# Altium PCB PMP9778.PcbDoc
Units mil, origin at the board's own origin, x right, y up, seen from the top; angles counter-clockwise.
Board outline 1070 x 670 mil, 4 copper layers (Top Layer, GND1, GND2, Bottom Layer), stack 82.634 mil thick; 30 components, 18 nets, 77 pads, 46 vias.
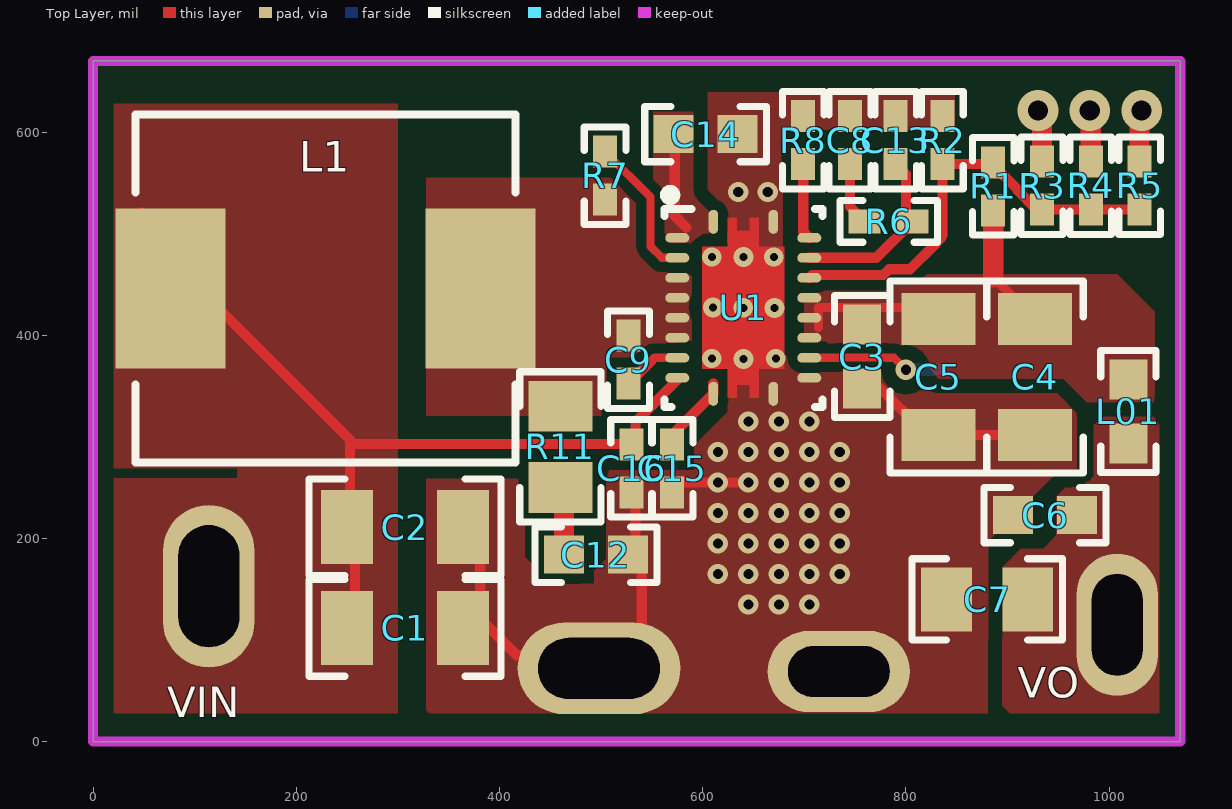
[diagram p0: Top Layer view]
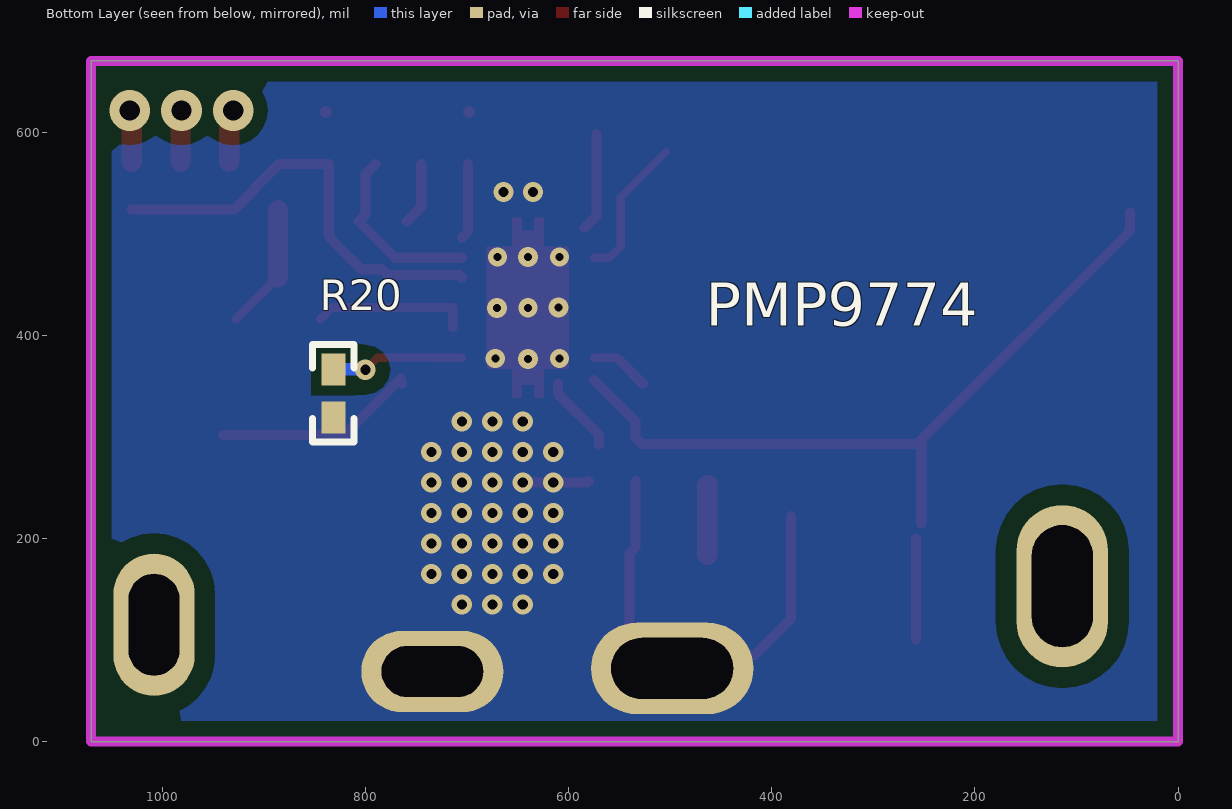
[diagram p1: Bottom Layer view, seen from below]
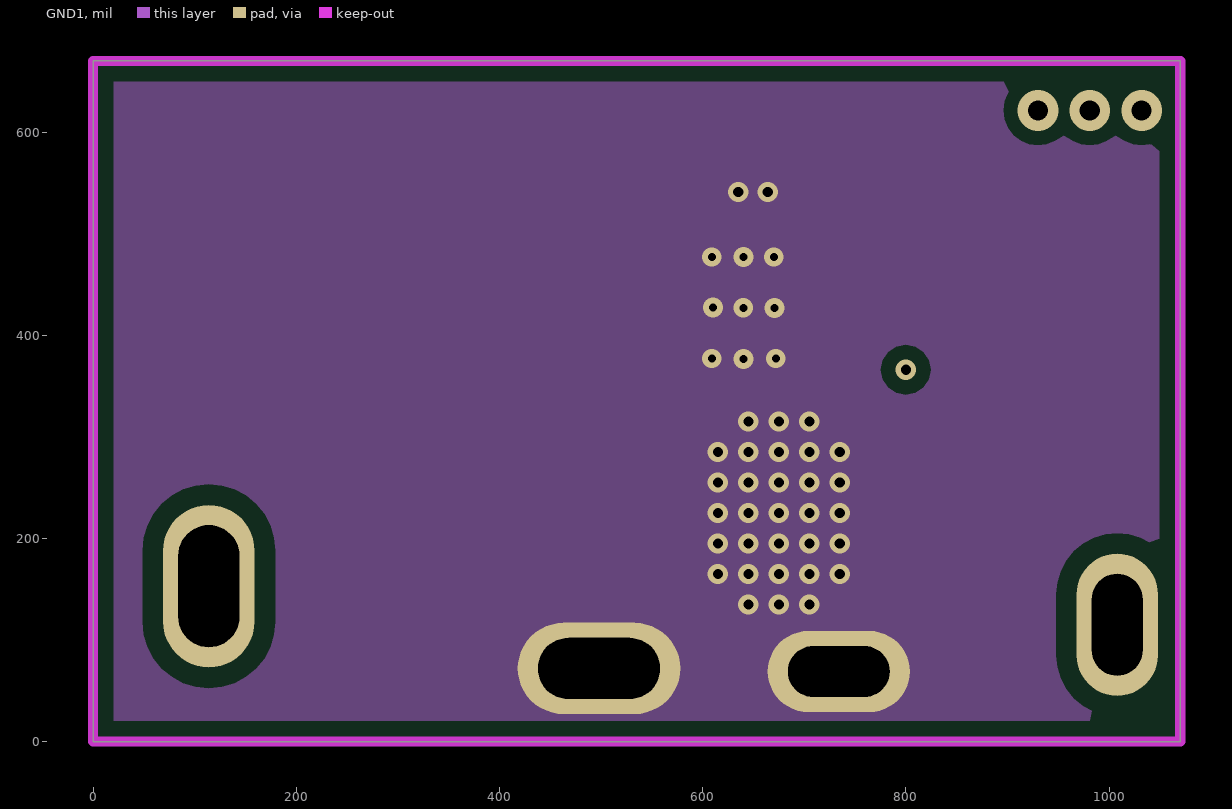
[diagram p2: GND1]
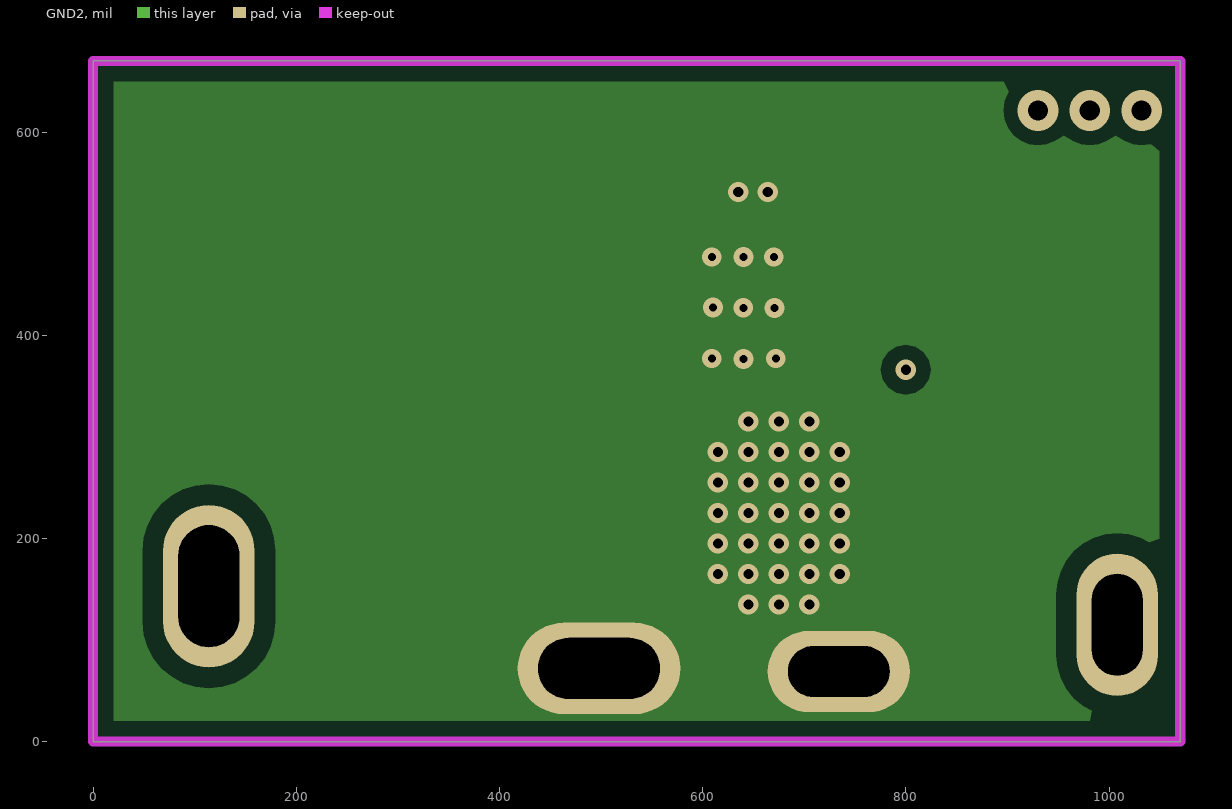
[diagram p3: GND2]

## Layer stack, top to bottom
Top Solder: solder mask 0.4, Solder Resist, Dk 3.5
Top Layer: signal copper 2.8
Dielectric1: core 59.2, FR-4, Dk 4.8
GND1: signal copper 1.417
Dielectric 3: prepreg 5, Dk 4.2
GND2: signal copper 1.417
Dielectric 2: core 10, Dk 4.2
Bottom Layer: signal copper 2.8
Bottom Solder: solder mask 0.4, Solder Resist, Dk 3.5

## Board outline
0,0 0,670 1070,670 1070,0

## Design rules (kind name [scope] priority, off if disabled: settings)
AcuteAngle [All] p1: minimum=4.50000000000000E+0001 checktracksonly=FALSE
AssemblyTestPointUsage [All] p1: valid=2
Clearance Clearance_BoardEdge_MountingHoles [OnCopper and InComponentClass('Mounting Holes') vs IsKeepOut] p1: gap=40
Clearance Clearance_BoardEdge_Poly [OnCopper and InPoly vs IsKeepOut] p2: gap=20 except(15: Arc-Poly Track-Poly SMDPad-Poly THPad-Poly Via-Poly Fill-Poly Poly-Poly Poly-Region Poly-Text)
Clearance Clearance_BoardEdge [All vs IsKeepOut] p3 off: gap=75
Clearance Clearance_Poly [InPolygon] p4: gap=20 except(10: Track-Poly SMDPad-Poly Poly-Region; 14: Via-Poly Fill-Poly Poly-Poly)
Clearance [All] p5: gap=7 except(5: THPad-Via Via-Via)
ComponentClearance ComponentClearance_Logo [InComponentClass('Logo')] p1: gap=50 collisioncheckmode=3 verticalgap=10 showdistances=FALSE
ComponentClearance ComponentClearance_ScrewToNut [(HasFootprint('NY PMS 440 0025 PH')) vs (HasFootprint('Keystone_1902C'))] p2: gap=0.5 collisioncheckmode=3 verticalgap=0.5 showdistances=FALSE
ComponentClearance ComponentClearance_MountingHoles [InComponentClass('Mounting Holes')] p3 off: gap=250 collisioncheckmode=3 verticalgap=100000 showdistances=FALSE
ComponentClearance ComponentClearance_SmallPassives [HasFootprint('0201*') or HasFootprint('0402*') or HasFootprint('0508') or HasFootprint('0603*') or HasFootprint('0612') or HasFootprint('0805*') or HasFootprint('0815*') or HasFootprint('0830*') or HasFootprint('1206*') or HasFootprint('1210*') or HasFootprint('1808*') or HasFootprint('1812*') or HasFootprint('1825*') or HasFootprint('2010*') or HasFootprint('2220*') or HasFootprint('2225*') or HasFootprint('2512*') or HasFootprint('2728*') or HasFootprint('3518*') vs HasFootprint('0201*') or HasFootprint('0402*') or HasFootprint('0508') or HasFootprint('0603*') or HasFootprint('0612') or HasFootprint('0805*') or HasFootprint('0815*') or HasFootprint('0830*') or HasFootprint('1206*') or HasFootprint('1210*') or HasFootprint('1808*') or HasFootprint('1812*') or HasFootprint('1825*') or HasFootprint('2010*') or HasFootprint('2220*') or HasFootprint('2225*') or HasFootprint('2512*') or HasFootprint('2728*') or HasFootprint('3518*')] p4: gap=5 collisioncheckmode=3 verticalgap=5 showdistances=FALSE
ComponentClearance ComponentClearance_THtoSMT [IsThruComponent vs IsSMTComponent] p5: gap=5 collisioncheckmode=3 verticalgap=5 showdistances=FALSE
ComponentClearance ComponentClearance_THtoTH [IsThruComponent vs IsThruComponent] p6: gap=5 collisioncheckmode=3 verticalgap=30 showdistances=FALSE
ComponentClearance [All] p7: gap=5 collisioncheckmode=3 verticalgap=5 showdistances=FALSE
DiffPairsRouting [All] p1: maxlimit=100 minlimit=10 mostfreqgap=10 toplayer_minwidth=15 toplayer_maxwidth=15 toplayer_prefwidth=15 midlayer1_minwidth=15 midlayer1_maxwidth=15 midlayer1_prefwidth=15 midlayer2_minwidth=15 midlayer2_maxwidth=15 midlayer2_prefwidth=15 bottomlayer_minwidth=15 bottomlayer_maxwidth=15 bottomlayer_prefwidth=15 maxuncoupledlength=1000
FabricationTestPointUsage TestPointUsage [All] p1: valid=2 allowmultiple=FALSE
FabricationTestpoint Testpoint [All] p1: side=3 testpointundercomponent=TRUE minsize=40 maxsize=100 preferedsize=60 minholesize=0 maxholesize=40 preferedholesize=32 testpointgrid=1 allowsidetop=TRUE allowsidebottom=TRUE usegrid=TRUE gridtolerance=0.01
FanoutControl Fanout_LCC [IsLCC] p1: bgadir=Out bgaviamode=Centered fanoutstyle=Auto fanoutdirection=Alternating viagrid=1 // Fanout_LCC (Default Rule)
FanoutControl Fanout_BGA [IsBGA] p2: bgadir=Out bgaviamode=Centered fanoutstyle=Auto fanoutdirection=Alternating viagrid=1 // Fanout_BGA (Default Rule)
FanoutControl Fanout_Default [All] p4: bgadir=Out bgaviamode=Centered fanoutstyle=Auto fanoutdirection=Alternating viagrid=1 // Fanout_Default (Default Rule)
FanoutControl Fanout_Small [(CompPinCount < 5)] p5: bgadir=Out bgaviamode=Centered fanoutstyle=Auto fanoutdirection=OutThenIn viagrid=1 // Fanout_Small (Default Rule)
HoleSize [All] p1: absolutevalues=TRUE maxlimit=251 minlimit=7.87 maxpercent=80.000 minpercent=20.000
MinimumAnnularRing MinimumAnnularRing_ThermalPadVias [IsVia and InAnyComponent] p1: minimumring=5.91
MinimumAnnularRing [All] p2: minimumring=5
MinimumSolderMaskSliver MinimumSolderMaskSliver_Logo [InComponentClass('Logo') vs InComponentClass('Logo')] p1: minsoldermaskwidth=0.7
MinimumSolderMaskSliver [All] p2: minsoldermaskwidth=4
PlaneConnect [All] p1: planeconnectstyle=Direct reliefexpansion=10 reliefentries=4 reliefconductorwidth=10 reliefairgap=10
PolygonConnect PolygonConnect_5 [All vs IsNamedPolygon('Top Layer-No Net')] p1: connectstyle=Direct reliefconductorwidth=10 reliefentries=4 polygonreliefangle="90 Angle" airgapwidth=10
PolygonConnect PolygonConnect_4 [All] p2: connectstyle=Direct reliefconductorwidth=10 reliefentries=4 polygonreliefangle="90 Angle" airgapwidth=10
PolygonConnect PolygonConnect_3 [All vs IsNamedPolygon('Top Layer-No Net')] p3: connectstyle=Direct reliefconductorwidth=10 reliefentries=4 polygonreliefangle="90 Angle" airgapwidth=10
PolygonConnect PolygonConnect_2 [All vs IsNamedPolygon('Bottom Layer-No Net')] p4: connectstyle=Direct reliefconductorwidth=10 reliefentries=4 polygonreliefangle="90 Angle" airgapwidth=10
PolygonConnect PolygonConnect_1 [All vs IsNamedPolygon('Bottom Layer-No Net')] p5: connectstyle=Direct reliefconductorwidth=10 reliefentries=4 polygonreliefangle="90 Angle" airgapwidth=10
PolygonConnect [All] p6: connectstyle=Direct reliefconductorwidth=10 reliefentries=4 polygonreliefangle="90 Angle" airgapwidth=10
RoutingVias ThermalPadVias [IsVia and InAnyComponent] p1: holewidth=7.87 width=19.68 viastyle="Through Hole" minholewidth=7.87 minwidth=19.68 maxholewidth=12.99 maxwidth=23.62
RoutingVias [All] p2: holewidth=16 width=34 viastyle="Through Hole" minholewidth=7.87 minwidth=16 maxholewidth=40 maxwidth=65
SMDToCorner [All] p1 off: distance=30000
SilkToBoardRegionClearance [All] p1 off:
SilkToSilkClearance SilkToSilkClearance_PB-Free [(HasFootprint('Pb-Free_Overlay_Medium') OR HasFootprint('Pb-Free_Overlay_Small')) vs (HasFootprint('Pb-Free_Overlay_Medium') OR HasFootprint('Pb-Free_Overlay_Small'))] p1: silktosilkclearance=0
SilkToSilkClearance [All] p2: silktosilkclearance=4
SilkToSolderMaskClearance SilkscreenOverComponentPads [IsPad] p1: minsilkscreentomaskgap=3 clearancetoexposedcopper=TRUE
SolderMaskExpansion [All] p1: expansion=1
Width [All] p1: maxlimit=100 minlimit=6 preferedwidth=10 checkconnectedcopper=TRUE
15 further rules are at their usual default settings.

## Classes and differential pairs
component class Reference2_Hardware: !PCB ZZ1 ZZ2 ZZ3
component class Reference2: C1 C2 C4 C5 C6 C7 C8 C9 C12 C13 C14 C15 C16 L1 L01 R1 R2 R3 R4 R5 R6 R7 R8 R11 R20 U1
component class AssemblyNote: ZZ1 ZZ2 ZZ3

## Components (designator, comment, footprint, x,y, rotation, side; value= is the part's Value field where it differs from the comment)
C1 "GRM31CR61C226KE15L" 1206 307,112 r0 top
C2 "GRM31CR61C226KE15L" 1206 307,211 r0 top
C3 "GRM188R71E105KA12D" 0603 757,379 r270 top
C4 "GRM31CR61C226KE15L" 1206 927,359 r270 top
C5 "GRM31CR61C226KE15L" 1206 832,359 r270 top
C6 "GRM188R71E103KA01D" 0603 937,223 r180 top
C7 "GRM219R61E106KA12" 0805_HV 880,140 r180 top
C8 "GRM155R61H472KA01D" 0402 745,592 r90 top
C9 "GRM155R61C104KA88D" 0402 527,376 r270 top
C12 "GRM1885C1H222JA01D" 0603 495,184 r0 top
C13 "GRM1555C1H470FA01D" 0402 790,592 r90 top
C14 "0603ZD475KAT2A" 0603 603,598 r180 top
C15 "GRM155R71C473KA01D" 0402 570,269 r90 top
C16 "GRM155R61C104KA88D" 0402 530,269 r270 top
L1 "CDMC8D28NP-1R2MC" CDMC8D28 225,445 r0 top
L01 "BLM18SG121TN1D" 0603 1019,325 r270 top
R1 "CRCW0402768KFKED" 0402 886,546.62 r270 top
R2 "CRCW0402120KFKED" 0402 836,592 r270 top
R3 "CRCW0402120KFKED" 0402 934,547.24 r270 top
R4 "CRCW0402120KFKED" 0402 982,547.24 r270 top
R5 "CRCW0402100KFKED" 0402 1030,547.24 r90 top
R6 "CRCW040217K4FKED" 0402 783,512 r0 top
R7 "CRCW0402330KJNED" 0402 504,557 r270 top
R8 "CRCW0402100KFKED" 0402 699,592 r270 top
R11 "CRCW08051R00FKEA" 0805_HV 460,290 r270 top
R20 "RC0402JR-070RL" 0402 831.58,342.88 r90 bottom
U1 "TPS61088RHLR" RHL0020A 640,427 r0 top
ZZ1 "These assemblies are ESD sensitive, ESD precautions shall be observed." AssemblyNote 4010,3305 r90 top
ZZ2 "These assemblies must be clean and free from flux and all contaminants. Use of no clean flux is not acceptable." AssemblyNote 4005,2895 r90 top
ZZ3 "These assemblies must comply with workmanship standards IPC-A-610 Class 2, unless otherwise specified." AssemblyNote 4010,2475 r90 top

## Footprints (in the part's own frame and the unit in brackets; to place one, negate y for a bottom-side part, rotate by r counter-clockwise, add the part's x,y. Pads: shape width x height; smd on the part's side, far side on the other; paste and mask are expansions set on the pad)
0402 [mm] "0402 from SM-752 data"
  rect 0.8x0.6 smd: 1(-0.6,0) 2(0.6,0)
  silkscreen extent -1.22,-0.52 1.22,0.52, body extent -0.55,-0.3 0.55,0.3, height 0.6
0603 [mm] "0603 from SM-752 data"
  rect 1x0.95 smd: 1(-0.8,0) 2(0.8,0)
  silkscreen extent -1.52,-0.69 1.52,0.69, body extent -0.87,-0.47 0.87,0.47, height 1
0805_HV [mil] "0805 with 30mil clearance between pads"
  rect 50x63 smd: 1(-40,0) 2(40,0)
  silkscreen extent -74,-40 74,40, body extent -43,-29 43,29, height 57
1206 [mm] "1206 from SM-752 data"
  rect 1.3x1.85 smd: 1(-1.45,0) 2(1.45,0)
  silkscreen extent -2.4,-1.21 2.4,1.21, body extent -1.7,-0.9 1.7,0.9, height 1.35
AssemblyNote [mil] "Assembly Note"
CDMC8D28 [mm] "SMD, 2-Leads, Body 9.5x8.7mm"
  rect 2.75x4 smd: 1(-3.773,0.025) 2(3.977,0.025)
  silkscreen extent -4.65,-4.32 4.85,4.38, body extent -4.65,-4.32 4.85,4.38, height 3
RHL0020A [mm] "QFN, 20-Leads, Body 4.5x3.5mm, Pitch 0.5mm, Thermal Pad 3.05x2.05mm, TI Recommended"
  oval 0.24x0.6 smd: 1(-0.75,2.15) 10(-0.75,-2.15) 11(0.75,-2.15) 20(0.75,2.15)
  oval 0.6x0.24 smd: 2(-1.65,1.75) 3(-1.65,1.25) 4(-1.65,0.75) 5(-1.65,0.25) 6(-1.65,-0.25) 7(-1.65,-0.75) 8(-1.65,-1.25) 9(-1.65,-1.75) 12(1.65,-1.75) 13(1.65,-1.25) 14(1.65,-0.75) 15(1.65,-0.25) 16(1.65,0.25) 17(1.65,0.75) 18(1.65,1.25) 19(1.65,1.75)
  rect 0.3x0.3 smd paste-0.15 mask+0: 21(0,0)
  Top Layer region: 0.16,2.25 0.16,1.925 -0.16,1.925 -0.16,2.25 -0.39,2.25 -0.39,1.525 -1.025,1.525 -1.025,-1.525 -0.39,-1.525 -0.39,-2.25 -0.16,-2.25 -0.16,-1.925 0.16,-1.925 0.16,-2.25 0.39,-2.25 0.39,-1.525 1.025,-1.525 1.025,1.525 0.39,1.525 0.39,2.25
  silkscreen extent -1.98,-2.47 1.98,2.47, body extent -1.82,-2.33 1.83,2.32, height 1.01

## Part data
C1 C2 C4 C5: "CAP, CERM, 22 µF, 16 V, +/- 10%, X5R, 1206"
C3: "CAP, CERM, 1 µF, 25 V, +/- 10%, X7R, 0603"
C6: "CAP, CERM, 0.01 µF, 25 V, +/- 10%, X7R, 0603"
C7: "CAP, CERM, 10 µF, 25 V, +/- 10%, X5R, 0805"
C8: "CAP, CERM, 4700 pF, 50 V, +/- 10%, X5R, 0402"
C9 C16: "CAP, CERM, 0.1uF, 16V, +/-10%, X5R, 0402"
C12: "CAP, CERM, 2200 pF, 50 V, +/- 5%, C0G/NP0, 0603"
C13: "CAP, CERM, 47 pF, 50 V, +/- 1%, C0G, 0402"
C14: "CAP, CERM, 4.7uF, 10V, +/-10%, X5R, 0603"
C15: "CAP, CERM, 0.047 µF, 16 V, +/- 10%, X7R, 0402"
L1: "Inductor, Shielded Drum Core, Metal Composite, 1.2 µH, 12.9 A, 0.007 ohm, SMD"
L01: "Ferrite Bead, 120 ohm @ 100 MHz, 3 A, 0603"
R1: "RES, 768 k, 1%, 0.063 W, 0402"
R2 R3 R4: "RES, 120 k, 1%, 0.063 W, 0402"
R5 R8: "RES, 100k ohm, 1%, 0.063W, 0402"
R6: "RES, 17.4k ohm, 1%, 0.063W, 0402"
R7: "RES, 330 k, 5%, 0.063 W, 0402"
R11: "RES, 1.00, 1%, 0.125 W, 0805"
R20: "RES, 0, 5%, 0.063 W, 0402"
U1: "13.2-V Output, Synchronous Boost Converter with 10-A Switch, RHL0020A"
ZZ1 ZZ2 ZZ3: library part AssemblyNote

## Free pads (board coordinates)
  oval 90x160 hole 60 slot 120 at 90 deg: 0(114,153)
  oval 160x90 hole 60 slot 120 at 0 deg: 0(498,72)
  oval 140x80 hole 50 slot 100 at 0 deg: 0(734,69)
  oval 80x140 hole 50 slot 100 at 90 deg: 0(1008,115)

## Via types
v1: diameter 20, hole 10, Top Layer to Bottom Layer, 34 vias
v2: diameter 19, hole 7.87, Top Layer to Bottom Layer, 5 vias
v3: diameter 19.68, hole 7.87, Top Layer to Bottom Layer, 4 vias
v4: diameter 40, hole 20, Top Layer to Bottom Layer, 3 vias

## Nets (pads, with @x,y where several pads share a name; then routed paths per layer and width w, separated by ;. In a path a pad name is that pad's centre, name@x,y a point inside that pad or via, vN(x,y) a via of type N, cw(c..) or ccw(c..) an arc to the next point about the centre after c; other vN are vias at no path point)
AGND: C1.2 C2.2 C3.2 C4.2 C5.2 C6.2 C7.2 C8.2 C12.2 C13.2 C14.1 C15.1 C16.2 pad.0@498,72 pad.0@734,69 R2.1 R8.1 R20.1 U1.11 U1.12 U1.20 U1.21 | length 716.4
  Top Layer w10: C2.2@381.09,222 381.09,121 417.09,85 540,85 540,185.5 534,191.5 C16.2@534,256.38 ; C15.1@580,256.38 581.38,255 v1(645,255) ; C3.2@763.85,352.35 C3.2@767,355.5 ; C3.2@765.23,357.27 C3.2@767,355.5 ; C4.2@940,301.91 820.59,301.91 C3.2@767,355.5
  other v1: 645,135 675,135 705,135 615,165 645,165 675,165 705,165 735,165 615,195 645,195 675,195 705,195 735,195 615,225 645,225 675,225 705,225 735,225 615,255 675,255 705,255 735,255 615,285 645,285 675,285 705,285 735,285 645,315 675,315 705,315 635,541 664,541
  other v2: 609,377 672,377 640,427 609,477 670,477
  other v3: 640,376.8 610.03,427.49 670.51,427 640,477.2
FB: R1.1 R2.2 R3.2 R4.2 R5.1 U1.17 | length 432.4
  Top Layer w10: U1.17 707.65,459.21 777.87,459.21 783.66,465 804.15,465 827.34,488.19 834.37,495.22 834.37,496.37 836,498 R2.2 885.15,568.38 909.81,543.72 909.81,542.7 928.89,523.62 R3.2 R4.2 R5.1
MODE: R20.2 U1.13 | length 132
  Top Layer w8: U1.13 733.34,377.78 733.74,378.19 780.26,378.19 780.66,377.78 788.22,377.78 v1(800,366)
  Bottom Layer w8: v1(800,366) v1@800.51,366.51
  Bottom Layer w12: v1@800.51,366.51 R20.2
NetC8_1: C8.1 R6.1 | length 62.3
  Top Layer w10: C8.1 745,526.38 R6.1
NetC9_2: C9.2 U1.8 | length 58.6
  Top Layer w8: 549.42,374.8 552.41,377.78 U1.8
  Top Layer w10: C9.2 549.42,374.8
NetC12_1: C12.1 R11.2 | length 73.5
  Top Layer w12: R11.2@460,256 R11.2@463.5,252.5
  Top Layer w20: C12.1 R11.2@463.5,252.5
NetC13_1: C13.1 R6.2 U1.18 | length 179.7
  Top Layer w10: U1.18 770.83,476.21 R6.2 800,518.62 800,558.38 C13.1
NetC15_2: C15.2 U1.10 | length 75.5
  Top Layer w10: C15.2 570,301.88 U1.10 ; U1.10@610.48,343.35 U1.10@610.48,352.35
NetR7_1: R7.1 U1.3 | length 142.8
  Top Layer w8: R7.1 548.62,536 548.62,487.38 559.79,476.21 U1.3
NetR8_2: R8.2 U1.19 | length 75
  Top Layer w10: R8.2 699,501.86 U1.19
SW: C9.1 L1.2 R7.2 R11.1 U1.4 U1.5 U1.6 U1.7
V1: R3.1 | length 52
  Top Layer w12: v4(930,621.24) v4@934,617.24
  Top Layer w20: R3.1 v4@934,617.24
V2: R4.1 | length 50.8
  Top Layer w12: v4(981,621.24) v4@982,620.24
  Top Layer w20: R4.1 v4@982,620.24
V3: R5.2 | length 51.2
  Top Layer w12: v4@1030,619.24 v4(1032,621.24)
  Top Layer w20: R5.2 v4@1030,619.24
VCC: C14.2 U1.1 U1.2 | length 96.9
  Top Layer w10: C14.2@572.5,598 572.5,517.43 584.04,505.89
VIN: C1.1 C2.1 C16.1 L1.1 pad.0@114,153 U1.9 | length 845
  Top Layer w10: L1.1@47.44,520.47 47.44,502.56 252.91,297.09 C2.1@252.91,215 ; 255.91,293 528,293 534,299 534,314.85 U1.9@575.04,355.89 ; C1.1@257.91,100 C2.1@257.91,200
VO: C3.1 C4.1 C5.1 L01.1 R1.2 U1.14 U1.15 U1.16 | length 278.2
  Top Layer w9: 713.96,407.47 713.96,427.15 832.93,427.15 C5.1@844,416.09 ; 886,457.09 C4.1
  Top Layer w20: 886,457.09 R1.2
VO+: C6.1 C7.1 L01.2 pad.0@1008,115

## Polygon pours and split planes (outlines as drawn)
VIN on Top Layer "Top Layer-No Net" (solid, remove dead copper, pour order 2): 20.39,28 300,28 300,490 300,628 20.39,628
SW on Top Layer "Top Layer-No Net 1" (solid, remove dead copper, pour order 4): 327.81,554.75 548.62,554.75 548.62,498.75 581.62,465.75 591.62,465.75 591.62,394.75 579.12,394.75 576.12,394.75 562.12,380.75 561.12,379.75 561.12,360.75 561.12,359.75 558.12,356.75 554.12,352.75 525.12,352.75 518.12,345.75 500,327.63 500,320.75 327.81,320.75
AGND on Top Layer "AGND_L01_P006" (solid, remove dead copper, pour order 6): 624,482 624,524.23 605,543.23 605,579 605,639 848,639 848,602 759,602 679,602 679,483.24 625,482
VCC on Top Layer "VCC_L01_P008" (solid, remove dead copper, pour order 8): 594.27,620 594.27,541 594.27,534 610.27,518 624.27,518 625.27,518 625.27,485 570,485 551.27,503.73 551.27,560 551.27,620
VO on Top Layer "VO_L01_P010" (solid, remove dead copper, pour order 10): 1008,460 1045,423 1045,334 978,334 955,357 827,357 802,382 794,390 725,390 721,394 700,394 700,460
AGND on Top Layer "AGND_L01_P014" (solid, remove dead copper, pour order 14): 646,436.99 677,437 677,385.6 687.36,374 785,374 807,352 847,352 957,352 968,341 968,264 948,264 880.99,196.99 880.8,28 646,28
AGND on Top Layer "AGND_L01_P016" (solid, remove dead copper, pour order 16): 328,258.64 425,258.64 425,186 425,181.82 451.88,154.93 480.02,155.02 505,180 505,220 505,267 511,273 573,273 624.65,324.65 624.65,381.35 619.03,386.97 619.03,437.49 648.51,437.49 649,437 657,429 664,422 664,28 331,28 328,31
VO+ on Top Layer "VO+_L01_P028" (solid, remove dead copper, pour order 28): 980,320 1045,320 1050,320 1050,30 1050,28 894,28 894,170 894,171 903,180 913,190 935,190 943,198 946,201 948,203 948,241 963,256 980,256 985,261 985,319.92
AGND on GND1 "AGND_L02_P024" (solid, remove dead copper, pour order 24): -20,680 -10,690 1040,690 1050,680 1050,30 1040,20 -10,20 -20,30 -20,680
AGND on GND2 "AGND_L03_P026" (solid, remove dead copper, pour order 26): -20,680 -10,690 1040,690 1050,680 1050,30 1040,20 -10,20 -20,30 -20,680
AGND on Bottom Layer "AGND_L04_P030" (solid, remove dead copper, pour order 30): 20.39,649.61 20.39,20.39 20.78,20 1050,20 1050,650 1049.61,649.61 20.39,649.61

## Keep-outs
Keep-Out Layer:
  lines w10: 4394,3455 cw(c4394,3450) 4399,3450 ; 4394,3455 cw(c4394,3450) 4399,3450 ; 4394,3455 cw(c4394,3450) 4399,3450 ; 4394,3455 cw(c4394,3450) 4399,3450 ; 4394,3455 cw(c4394,3450) 4399,3450 ; 4394,3455 cw(c4394,3450) 4399,3450 ; 0,0 0,670 1070,670 1070,0 0,0
  text ".Layer_Name" at 21,-858.49 h30

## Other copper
Top Layer:
  pour cut-out: -10,269 142,269 142,259 -10,259
  text ".Layer_Name" at 21,-858.49 h30
Bottom Layer:
  text ".Layer_Name" at 21,-858.49 h30

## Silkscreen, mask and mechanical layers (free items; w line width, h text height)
Top Overlay:
  circle w10: c568,538 r5
  text "VO" at 910,43 h30
  text "VIN" at 73,24 h30
  text ".Layer_Name" at 21,-858.49 h30
Bottom Overlay:
  text "PMP9774" at 465,395 h72.83
  text ".Layer_Name" at 21,-858.49 h30
Top Paste:
  text ".Layer_Name" at 21,-858.49 h30
Bottom Paste:
  text ".Layer_Name" at 21,-858.49 h30
Top Solder:
  text ".Layer_Name" at 21,-858.49 h30
  text ".Layer_Name" at 21,-858.49 h30
Bottom Solder:
  text ".Layer_Name" at 21,-858.49 h30
Drill Guide:
  text ".Layer_Name" at 21,-858.49 h30
M1 Board Outline:
  the board outline again, w10
  text ".Layer_Name" at 21,-858.49 h30
M2 Board Dimensions:
  rectangle: -431.5,-410.5 -56.5,-285.5
  rectangle: -556.5,-285.5 -431.5,-160.5
  lines w7: -556.5,-285.5 443.5,-285.5 ; -431.5,-410.5 -431.5,-160.5 ; -306.5,-410.5 -306.5,-160.5 ; -56.5,-410.5 -56.5,-160.5 ; 193.5,-410.5 193.5,-160.5 ; -556.5,-410.5 -556.5,-160.5 443.5,-160.5 443.5,-410.5 -556.5,-410.5
  lines w10: -556.5,-475.5 -556.5,-455.5 ; -496.5,-485.5 -556.5,-465.5 ; -496.5,-445.5 -556.5,-465.5 ; -332.42,-465.5 -556.5,-465.5 ; -113.99,59.92 -93.99,-0.08 ; -113.99,609.92 -93.99,669.92 ; -103.99,-0.08 -83.99,-0.08 ; -103.99,669.92 -83.99,669.92 ; -93.99,84 -93.99,-0.08 ; -93.99,585.85 -93.99,669.92 ; -73.99,59.92 -93.99,-0.08 ; -73.99,609.92 -93.99,669.92 ; 0,-107 0,-87 ; 60,-117 0,-97 ; 60,-77 0,-97 ; 219.41,-465.5 443.5,-465.5 ; 259.08,-97 0,-97 ; 383.5,-485.5 443.5,-465.5 ; 383.5,-445.5 443.5,-465.5 ; 443.5,-475.5 443.5,-455.5 ; 810.92,-97 1070,-97 ; 1010,-117 1070,-97 ; 1010,-77 1070,-97 ; 1070,-107 1070,-87
  text "670 (mil)" at -58,94 h60 r90
  text "1070 (mil)" at 269.08,-132.99 h60
  text "1000 (mil)" at -322.42,-501.49 h60
  text ".Layer_Name" at 21,-858.49 h30
M3 3D STEP Top:
  text ".Layer_Name" at 21,-858.49 h30
M4 3D STEP Bottom:
  text ".Layer_Name" at 21,-858.49 h30
M5 Assembly Top:
  lines w10: -848,-930.17 5752,-930.17 ; -848,-726.83 5754,-726.83 ; -848,-523.5 -848,-1133.5 3157,-1133.5 5754,-1133.5 5754,-523.5 -847.5,-523.5 -847.5,-1133.5 728,-1133.5 ; 1617,-1133.5 1617,-523.5 ; 2884,-726.83 2884,-523.5 ; 3724,-726.83 3724,-523.5 ; 4346,-1140 4346,-937.17
  text "COMPONENTS MARKED 'DNP' SHOULD NOT BE POPULATED." at 597.5,-318.5 h30
  text "ASSEMBLY VARIANT:" at 597,-434 h30
  text ".VariantName" at 1633,-434 h30
  text "PCB VIEWED FROM TOP SIDE" at -784.5,-655.67 h30
  text "BOARD #:" at 1692,-655.67 h30
  text ".PRJ_Number" at 2237.5,-655.67 h30
  text "REV:" at 3082,-655.67 h30
  text ".PCB_Rev" at 3373.5,-655.67 h30
  text "SVN REV:" at 3920,-655.67 h30
  text ".VersionControl_RevNumber" at 4426,-655.67 h30
  text "IGNORE ->" at -784.5,-858.49 h30
  text "PLOT NAME =" at -784.5,-1064.34 h30
  text ".plot_File_Name" at 21,-1064.34 h30
  text "GENERATED    :" at 1694,-1064.34 h30
  text ".Print_Date" at 2563.5,-1064.34 h30
  text ".Print_Time" at 3292.5,-1064.34 h30
  text "TEXAS INSTRUMENTS" at 4557,-1064.34 h30
M6 Assembly Bottom:
  lines w10: -848.5,-727.33 5753.5,-727.33 ; -846.5,-930.67 5753.5,-930.67 ; 559.5,-1140.5 559.5,-937.67 ; 1181.5,-727.33 1181.5,-524 ; 2021.5,-727.33 2021.5,-524 ; 3288.5,-1134 3288.5,-524 ; 4177.5,-1134 5753,-1134 5753,-524 -848.5,-524 -848.5,-1134 1748.5,-1134 5753.5,-1134 5753.5,-524
  text "COMPONENTS MARKED 'DNP' SHOULD NOT BE POPULATED." at 5546,-318 h30
  text ".VariantName" at 4502,-434 h30
  text "ASSEMBLY VARIANT:" at 5541,-434 h30
  text ".VersionControl_RevNumber" at 479.5,-656.17 h30
  text "SVN REV:" at 985.5,-656.17 h30
  text ".PCB_Rev" at 1532,-656.17 h30
  text "REV:" at 1823.5,-656.17 h30
  text ".PRJ_Number" at 2668,-656.17 h30
  text "BOARD #:" at 3213.5,-656.17 h30
  text "PCB VIEWED FROM BOTTOM SIDE" at 5690,-656.17 h30
  text "IGNORE ->" at 1991.85,-858.49 h30
  text "TEXAS INSTRUMENTS" at 348.5,-1064.84 h30
  text ".Print_Time" at 1613,-1064.84 h30
  text ".Print_Date" at 2342,-1064.84 h30
  text "GENERATED    :" at 3211.5,-1064.84 h30
  text ".plot_File_Name" at 4884.5,-1064.84 h30
  text "PLOT NAME =" at 5690,-1064.84 h30
M9 Title Sheet:
  drawing of 57 lines, arcs and shapes, not listed
  text "1" at 183.84,8036.5 h30
  text "2" at 2679.5,8036.5 h30
  text "3" at 5168.84,8036.5 h30
  text "4" at 7675.51,8036.5 h30
  text "5" at 10174.5,8036.5 h30
  text "6" at 12679.5,8036.5 h30
  text "A" at -972.5,6893.5 h30
  text "A" at 13827.5,6893.5 h30
  text "B" at -972.5,4513.5 h30
  text "B" at 13827.5,4513.5 h30
  text "C" at -972.5,2138.5 h30
  text "C" at 13827.5,2138.5 h30
  text "PROJECT TITLE:" at 10787.5,277.5 h30
  text ".PRJ_Title" at 10837.5,144.17 h30
  text "DESIGNED FOR:" at 10787.5,-23.5 h30
  text ".PRJ_Customer" at 10837.5,-163.5 h30
  text "D" at -972.5,-231.5 h30
  text "D" at 13827.5,-231.5 h30
  text "FILE NAME:" at 10787.5,-323.5 h30
  text ".PCB_File_Name_No_Path" at 10837.5,-443.5 h30
  text "Texas Instruments (TI) and/or its licensors do not warrant the accuracy or completeness of this specification" at 5818,-605.34 h30
  text "ENGINEER:" at 10787.5,-613.5 h30
  text "LAYOUT BY:" at 12292.5,-613.5 h30
  text "or any information contained therein. TI and/or its licensors do not warrant that this design will meet" at 5773.01,-718 h30
  text ".PRJ_Engineer" at 10837.5,-768.49 h30
  text ".PCB_Layout" at 12343,-768.49 h30
  text "the specifications, will be suitable for your application or fit for any particular purpose, or will operate in" at 5773.01,-830.67 h30
  text ".Layer_Name" at 21,-858.49 h30
  text "ALTIUM DESIGNER VERSION:" at 12292.5,-923.5 h30
  text "an implementation. TI and/or its licensors do not warrant that the design is production worthy. You should" at 5773.01,-943.33 h30
  text "completely validate and test your design implementation to confirm the system functionality for your application." at 5818,-1056 h30
  text ".print_Scale" at 10837.5,-1056.83 h30
  text ".Application_BuildNumber" at 12343,-1056.83 h30
  text "1" at 183.84,-1263.5 h30
  text "2" at 2679.5,-1263.5 h30
  text "3" at 5168.84,-1263.5 h30
  text "4" at 7675.51,-1263.5 h30
  text "5" at 10174.5,-1263.5 h30
  text "6" at 12679.5,-1263.5 h30
M10 Fab Notes:
  drawing of 212 lines, arcs and shapes, not listed
  text "DESIGN INFORMATION" at 11825.02,6810 h30
  text "(REFER ALSO ARRAY/PANEL PROFILING INFORMATION)" at 11463.46,6648.29 h30
  text "BOARD SIZE" at 10777.46,6644 h30
  text "2300MIL" at 11239.78,6516.18 h30
  text "X" at 11745.46,6516.18 h30
  text "3100MIL" at 11976.78,6516.18 h30
  text "Number of Layers :" at 11180.46,6319 h30
  text "4" at 12275.27,6309 h30
  text "MIN. TRACK WIDTH:" at 11180.46,6180 h30
  text "8" at 12276.7,6180 h30
  text "MIL" at 12431.46,6180 h30
  text "MIN. CLEARANCE:" at 11180.46,6048 h30
  text "8" at 12276.7,6048 h30
  text "MIL" at 12431.46,6048 h30
  text "MIN. VIA PAD SIZE:" at 11180.46,5916 h30
  text "24" at 12246.71,5916 h30
  text "MIL" at 12431.46,5916 h30
  text "0.05mm (2MIL)" at 11875.46,5774.29 h30
  text "MINIMUM ANNULAR RING" at 10851.23,5770 h30
  text "EXTERNAL" at 12583.46,5770 h30
  text "PER" at 11051.23,5652 h30
  text "IPC-D-275 CLASS 2 LEVEL C" at 11271.23,5652 h30
  text "MIL, HOLES" at 12759.46,5539.71 h30
  text "+/-" at 12367,5539 h30
  text "+/-" at 13221,5539 h30
  text "REGISTRATION TOLERANCES:" at 10851.23,5534 h30
  text "METAL" at 12051,5534 h30
  text "5" at 12627.2,5534 h30
  text "3" at 13460.2,5534 h30
  text "MIL" at 13576.46,5534 h30
  text "MATERIAL:" at 10776.46,5324.54 h30
  text "FR-4 High Tg" at 11762.9,5184.21 h30
  text "FR-408" at 11197.46,5175.64 h30
  text "X" at 11609.46,5175.64 h30
  text "OTHER" at 12685.46,5175.64 h30
  text "X" at 12695,5025 h30
  text "62 MIL (1.6mm) +/-10%" at 11517.56,5012.92 h30
  text "1.2mm" at 13070,5010 h72.83
  text "THICKNESS:" at 10851.23,5008.64 h30
  text "OTHER" at 12802.46,5008.64 h30
  text "TOLERANCE:" at 10851.23,4850.64 h30
  text "X" at 11690.53,4850.64 h30
  text "ANSI IPC-6012 TYPE 3 CLASS 2" at 11877.47,4850.64 h30
  text "OTHER +/-" at 11877.46,4694.64 h30
  text "BOW & TWIST:" at 10851.23,4537.64 h30
  text "X" at 11690.53,4537.64 h30
  text "ANSI IPC-6012 TYPE 3 CLASS 2" at 11877.47,4537.64 h30
  text "OTHER +/-" at 11877.46,4379.13 h30
  text "COPPER THICKNESS (FINISHED):" at 10776.46,4243.64 h30
  text "1.4MIL (1oz)" at 11656.46,4090.92 h30
  text "2MIL (1.4oz)" at 12423.46,4090.92 h30
  text "2.8MIL (2oz)" at 13150.46,4090.92 h30
  text "X" at 13030,4089 h30
  text "OUTER:" at 11133.46,4086.64 h30
  text "1.4MIL (1oz)" at 11656.46,3933.92 h30
  text "2.8MIL (2oz)" at 12423.46,3933.92 h30
  text "N/A" at 13150,3934.29 h30
  text "INNER SIGNAL:" at 10844.38,3929.64 h30
  text "X" at 11529.42,3929.64 h30
  text "DRILLING:" at 10776.46,3790.64 h30
  text "REFERENCE:" at 10851.23,3673.64 h30
  text "X" at 11499.46,3673.64 h30
  text "AS SHOWN" at 11686.46,3673.64 h30
  text "X" at 12400.46,3673.64 h30
  text "NC_DRILL FILES" at 12537.46,3673.64 h30
  text "PTH MIN COPPER THICKNESS:" at 10851.23,3515.64 h30
  text "X" at 12201.46,3515.64 h30
  text "1MIL" at 12338.46,3515.64 h30
  text "OTHER" at 12835.46,3515.64 h30
  text "BOARD FINISH:" at 10776.46,3356.64 h30
  text "SILKSCREEN:" at 10931.68,3238.64 h30
  text "X" at 11880.46,3238.64 h30
  text "TOP" at 12006.46,3238.64 h30
  text "BOTTOM" at 12517.46,3238.64 h30
  text "SILKSCREEN COLOR:" at 10931.68,3071.64 h30
  text "X" at 11879.42,3071.64 h30
  text "WHITE" at 12006.46,3071.64 h30
  text "OTHER" at 12517.46,3071.64 h30
  text "SOLDER RESIST COLOR:" at 10931.68,2901.64 h30
  text "X" at 11499.42,2742.44 h30
  text "GREEN" at 11626.46,2742.44 h30
  text "BLUE" at 12217.46,2742.44 h30
  text "OTHER" at 12755.46,2742.44 h30
  text "IMMERSION GOLD (ENIG)" at 11837.46,2553.92 h30
  text "ENEPIG" at 13175,2550.64 h30
  text "SURFACE FINISH:" at 10776.46,2549.64 h30
  text "X" at 11650.51,2549.64 h30
  text "IMM. TIN/SILVER OR EQUIV" at 11106,2392.64 h30
  text "OTHER" at 12537.46,2392.64 h30
  text "ARRAY/PANEL:" at 10776.46,2213.64 h30
  text "CUT AND TRIM PER MECH LAYER 1" at 11837.46,2209.35 h30
  text "N.C. ROUTE" at 11837.46,2057.64 h30
  text "X" at 12516.46,2057.64 h30
  text "V. SCORE" at 12703.46,2057.64 h30
  text "CERTIFICATION:" at 10776.46,1920.64 h30
  text "MATERIALS AND WORKMANSHIP FOR ALL PCBS" at 11501.46,1920.64 h30
  text "TO MEET OR EXCEED THE REQUIREMENTS OF:" at 11501.46,1822.64 h30
  text "X" at 11127.96,1686.13 h30
  text "ANSI IPC-A-600F CLASS ->" at 11266.96,1686.13 h30
  text "X" at 12906.02,1686.13 h30
  text "2" at 13024.96,1686.14 h30
  text "1" at 12709.96,1684.64 h30
  text "3" at 13378.96,1684.64 h30
  text "X" at 11130.02,1526.64 h30
  text "UL 94V-0" at 11266.96,1526.64 h30
  text "X" at 11942.02,1526.64 h30
  text "RoHS" at 12078.96,1526.64 h30
  text "OTHER" at 12723.36,1526.64 h30
  text "PER ORDER" at 13120.42,1526.64 h30
  text "ADDITIONAL REQUIREMENTS:" at 10776.46,1385.64 h30
  text "MICROSECTION:" at 10851.23,1270.64 h30
  text "YES" at 11756.96,1270.64 h30
  text "REQUIRED" at 12618.46,1114.49 h30
  text "BARE BOARD ELEC. TEST:" at 10851.23,1111.64 h30
  text "NONE" at 12156.96,1111.64 h30
  text "PER ORDER" at 13210.46,1111.64 h30
  text "MANUFACTURER'S UL:" at 10851.23,954.64 h30
  text "RAIL" at 12016.96,950.35 h30
  text "METAL" at 12508.77,950.35 h30
  text "SILK" at 13020.46,950.35 h30
  text ".Layer_Name" at 21,-858.49 h30
M11 Gerber Information:
  lines w10: -848,-930.17 5752,-930.17 ; -848,-726.83 5754,-726.83 ; -848,-523.5 -848,-1133.5 3157,-1133.5 5754,-1133.5 5754,-523.5 -847.5,-523.5 -847.5,-1133.5 728,-1133.5 ; 1617,-1133.5 1617,-523.5 ; 2884,-726.83 2884,-523.5 ; 3724,-726.83 3724,-523.5 ; 4346,-1140 4346,-937.17
  text "ALL ARTWORK VIEWED FROM TOP SIDE" at -784.5,-655.67 h30
  text "BOARD #:" at 1692,-655.67 h30
  text ".PRJ_Number" at 2237.5,-655.67 h30
  text "REV:" at 3082,-655.67 h30
  text ".PCB_Rev" at 3373.5,-655.67 h30
  text "SVN REV:" at 3920,-655.67 h30
  text ".VersionControl_RevNumber" at 4426,-655.67 h30
  text "LAYER NAME =" at -784.5,-858.49 h30
  text "PLOT NAME =" at -784.5,-1064.34 h30
  text ".plot_File_Name" at 21,-1064.34 h30
  text "GENERATED    :" at 1694,-1064.34 h30
  text ".Print_Date" at 2563.5,-1064.34 h30
  text ".Print_Time" at 3292.5,-1064.34 h30
  text "TEXAS INSTRUMENTS" at 4557,-1064.34 h30
M12 Stackup:
  drawing of 165 lines, arcs and shapes, not listed
  text "Layer" at 8808,7414 h30
  text "Name" at 9018.96,7414 h30
  text "Material" at 9454.84,7414 h30
  text "Thickness" at 9890.72,7414 h30
  text "Constant" at 10221.64,7414 h30
  text "Board Layer Stack" at 10512.57,7414 h30
  text "1" at 8808,7354 h30
  text "Top Overlay" at 9018.96,7354 h30
  text "2" at 8808,7294 h30
  text "Top Solder" at 9018.96,7294 h30
  text "Solder Resist" at 9454.84,7294 h30
  text "0.40mil" at 9890.72,7294 h30
  text "3.5" at 10221.64,7294 h30
  text "3" at 8808,7234 h30
  text "Top Layer" at 9018.96,7234 h30
  text "Copper" at 9454.84,7234 h30
  text "2.80mil" at 9890.72,7234 h30
  text "4" at 8808,7174 h30
  text "Dielectric1" at 9018.96,7174 h30
  text "FR-4" at 9454.84,7174 h30
  text "59.20mil" at 9890.72,7174 h30
  text "4.8" at 10221.64,7174 h30
  text "5" at 8808,7114 h30
  text "Bottom Layer" at 9018.96,7114 h30
  text "Copper" at 9454.84,7114 h30
  text "2.80mil" at 9890.72,7114 h30
  text "6" at 8808,7054 h30
  text "Bottom Solder" at 9018.96,7054 h30
  text "Solder Resist" at 9454.84,7054 h30
  text "0.40mil" at 9890.72,7054 h30
  text "3.5" at 10221.64,7054 h30
  text ".Layer_Name" at 21,-858.49 h30
M13 Component Bodies Top:
  text ".Layer_Name" at 21,-858.49 h30
M14 Component Bodies Bottom:
  text ".Layer_Name" at 21,-858.49 h30
M15 Courtyards Top:
  text ".Layer_Name" at 21,-858.49 h30
M16 Courtyards Bottom:
  text ".Layer_Name" at 21,-858.49 h30
Drill Drawing:
  circle w8: c3762.31,774.34 r16.67
  lines w8: 3745.64,607.67 3778.98,607.67 3778.98,641 3745.64,641 3745.64,607.67 ; 3745.64,691 3753.98,691 3753.98,682.67 3770.64,682.67 3770.64,691 3778.98,691 3778.98,707.67 3770.64,707.67 3770.64,716 3753.98,716 3753.98,707.67 3745.64,707.67 3745.64,691 ; 3745.64,841 3753.98,841 3762.31,832.67 3770.64,841 3778.98,841 3770.64,849.34 3778.98,857.67 3770.64,857.67 3762.31,866 3753.98,857.67 3745.64,857.67 3753.98,849.34 3745.64,841 ; 3745.64,907.67 3762.31,916 3778.98,907.67 3770.64,924.34 3778.98,941 3762.31,932.67 3745.64,941 3753.98,924.34 3745.64,907.67
  lines w15: 3714.81,585.17 5702.3,585.17 ; 3714.81,960.17 5702.3,960.17 ; 3999.85,510.17 3999.85,1035.17 ; 4358.36,510.17 4358.36,1035.17 ; 5040.76,510.17 5040.76,1035.17 ; 5303.3,510.17 5303.3,1035.17 ; 3714.81,510.17 5702.3,510.17 5702.3,1035.17 3714.81,1035.17 3714.81,510.17
  text "Symbol" at 3759.81,982.67 h36
  text "Hit Count" at 4022.35,982.67 h36
  text "Finished Hole Size" at 4380.86,982.67 h36
  text "Plated" at 5063.26,982.67 h36
  text "Hole Type" at 5325.8,982.67 h36
  text "2" at 4022.35,907.67 h30
  text "50.00mil (1.270mm)" at 4380.86,907.67 h30
  text "PTH" at 5063.26,907.67 h30
  text "Slot" at 5325.8,907.67 h30
  text "2" at 4022.35,832.67 h30
  text "60.00mil (1.524mm)" at 4380.86,832.67 h30
  text "PTH" at 5063.26,832.67 h30
  text "Slot" at 5325.8,832.67 h30
  text "3" at 4022.35,757.67 h30
  text "20.00mil (0.508mm)" at 4380.86,757.67 h30
  text "PTH" at 5063.26,757.67 h30
  text "Round" at 5325.8,757.67 h30
  text "9" at 4022.35,682.67 h30
  text "7.87mil (0.200mm)" at 4380.86,682.67 h30
  text "PTH" at 5063.26,682.67 h30
  text "Round" at 5325.8,682.67 h30
  text "34" at 4022.35,607.67 h30
  text "10.00mil (0.254mm)" at 4380.86,607.67 h30
  text "PTH" at 5063.26,607.67 h30
  text "Round" at 5325.8,607.67 h30
  text "50 Total" at 4022.35,532.67 h30
  text "Slot definitions :" at 3759.81,454.18 h30
  text "Routed Path Length" at 4284.56,454.18 h30
  text "= Calculated from tool start centre position to tool end centre position." at 4844.29,454.18 h30
  text "Hole Length" at 4284.56,398.2 h30
  text "= Routed Path Length + Tool Size = Slot length as defined in the PCB layout" at 4639.36,398.2 h30
  text ".Layer_Name" at 21,-858.49 h30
